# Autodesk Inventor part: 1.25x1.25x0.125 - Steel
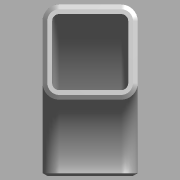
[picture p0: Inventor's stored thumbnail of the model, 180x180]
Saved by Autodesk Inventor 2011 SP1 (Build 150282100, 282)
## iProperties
Created: 2011-03
Part Number: 1.25x1.25x0.125 - Steel
Material: Default
Document SubType Name: Modeling
Designer: bamfomg
Density: 1 g/cm^3
Author: bamfomg
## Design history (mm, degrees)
derived "Square Tube Corners.ipt" dims "d2" = 15.875, "d3" = 15.875, "d6" = 3.175, "d7" = 3.175, "d8" = 3.175, "d12" = 90 deg, "d16" = 1.5875, "d18" = 30 deg, "ID_Rad" = 2.38125, "OD_Rad" = 5.55625, "Side_One" = 31.75, "Side_Two" = 31.75, "Thickness" = 3.175, "Bend_IDRad" = 25.4, "Bevel_Angl" = 30 deg, "Bevel_Dist" = 1.5875
body "Solid1"
feature "Solid1::Square Tube Corners.ipt" dims "d2" = 15.875, "d3" = 15.875, "d6" = 3.175, "d7" = 3.175, "d8" = 3.175, "d12" = 90 deg, "d16" = 1.5875, "d18" = 30 deg, "ID_Rad" = 2.38125, "OD_Rad" = 5.55625, "Side_One" = 31.75, "Side_Two" = 31.75, "Thickness" = 3.175, "Bend_IDRad" = 25.4, "Bevel_Angl" = 30 deg, "Bevel_Dist" = 1.5875, "ScaleForDerivedMember" = 10
tag "TaggingFeature1"
